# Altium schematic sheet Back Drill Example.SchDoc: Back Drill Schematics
size 431 x 279 mm; Author: Sharp Edges; Organization: Altium Limited; Address1: L3, 12a Rodborough Rd; Address2: Frenchs Forest; Address3: NSW; Address4: Australia 2086; DocumentNumber: 1; Revision: 1.0; SheetNumber: 1; SheetTotal: 1
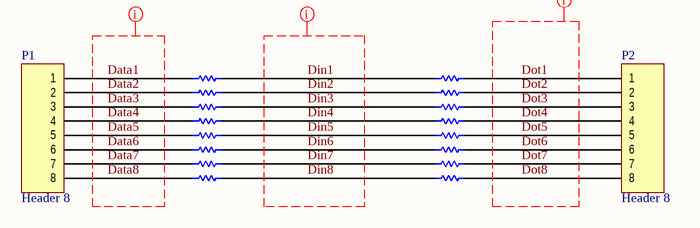
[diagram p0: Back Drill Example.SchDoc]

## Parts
P1  Header 8  [HDR1X8]
P2  Header 8  [HDR1X8]
R1  1K 0603  [0603_L]  (value not drawn)
R2  1K 0603  [0603_L]  (value not drawn)
R3  1K 0603  [0603_L]  (value not drawn)
R4  1K 0603  [0603_L]  (value not drawn)
R5  1K 0603  [0603_L]  (value not drawn)
R6  1K 0603  [0603_L]  (value not drawn)
R7  1K 0603  [0603_L]  (value not drawn)
R8  1K 0603  [0603_L]  (value not drawn)
RS1  1K 0603  [0603_L]  (value not drawn)
RS2  1K 0603  [0603_L]  (value not drawn)
RS3  1K 0603  [0603_L]  (value not drawn)
RS4  1K 0603  [0603_L]  (value not drawn)
RS5  1K 0603  [0603_L]  (value not drawn)
RS6  1K 0603  [0603_L]  (value not drawn)
RS7  1K 0603  [0603_L]  (value not drawn)
RS8  1K 0603  [0603_L]  (value not drawn)

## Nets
Data1: P1.1 R1.1
Data2: P1.2 R2.1
Data3: P1.3 R3.1
Data4: P1.4 R4.1
Data5: P1.5 R5.1
Data6: P1.6 R6.1
Data7: P1.7 R7.1
Data8: P1.8 R8.1
Din1: R1.2 RS1.1
Din2: R2.2 RS2.1
Din3: R3.2 RS3.1
Din4: R4.2 RS4.1
Din5: R5.2 RS5.1
Din6: R6.2 RS6.1
Din7: R7.2 RS7.1
Din8: R8.2 RS8.1
Dot1: P2.1 RS1.2
Dot2: P2.2 RS2.2
Dot3: P2.3 RS3.2
Dot4: P2.4 RS4.2
Dot5: P2.5 RS5.2
Dot6: P2.6 RS6.2
Dot7: P2.7 RS7.2
Dot8: P2.8 RS8.2

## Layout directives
net class HSdata: Data1, Data2, Data3, Data4, Data5, Data6, Data7, Data8, Din1, Din2, Din3, Din4, Din5, Din6, Din7, Din8, Dot1, Dot2, Dot3, Dot4, Dot5, Dot6, Dot7, Dot8

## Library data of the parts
P1 P2 = Header 8: Header, 8-Pin
R1-R8 RS1-RS8 = Res1K_0603: Manufacturer: Panasonic Electronic Components; Manufacturer Part Number: ERJ-3GEYJ102V; Tolerance: ±5%; Power (Watts): 0.1W, 1/10W; Temperature Coefficient: ±200ppm/°C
